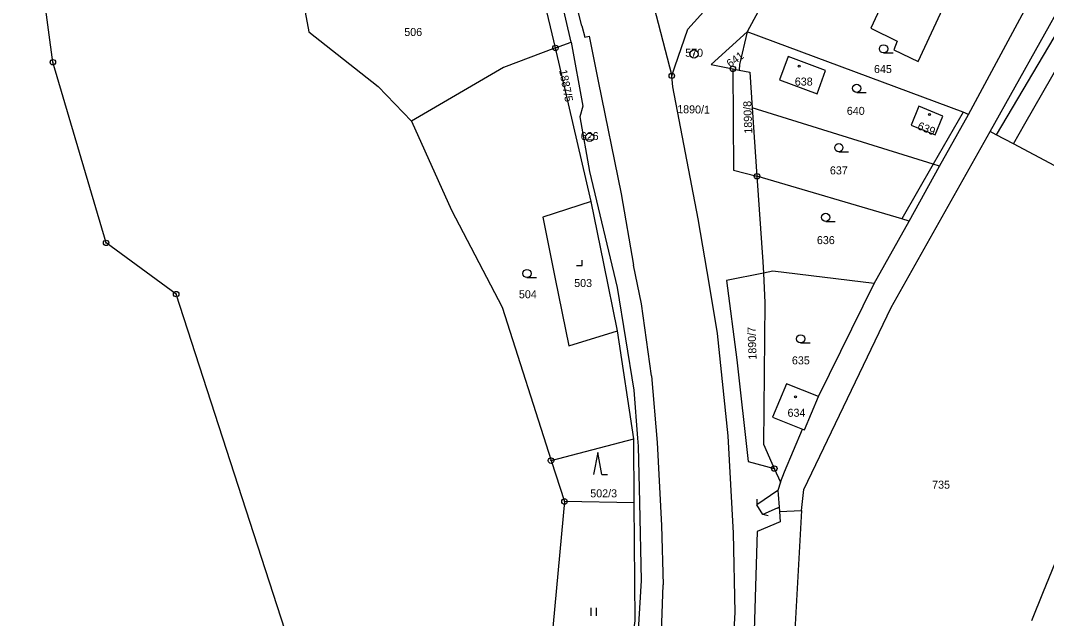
# Model space of a CAD drawing. Extents: x -587171 to -555306, y -1167727 to -1074732.
# Drawn here: x -561154 to -560966.9, y -1078245.7 to -1078136.7 of the extents above; entities that cross this region are included whole.
import ezdxf

# ---------------------------------------------------------------- set-up
doc = ezdxf.new("R2010")
doc.units = 0
for name, color, linetype in [('Hranice parcel', 7, 'Continuous'), ('Parcelní čísla', 7, 'Continuous'), ('Vnitřní kresba', 7, 'Continuous'), ('Značky bodu BP', 7, 'Continuous'), ('Značky budov', 7, 'Continuous'), ('Značky kultur', 7, 'Continuous')]:
    doc.layers.add(name, color=color, linetype=linetype)

msp = doc.modelspace()

# ---------------------------------------------------------------- linework, layer by layer
at = {"layer": 'Hranice parcel'}
for p, q in [((-560977.13, -1078156.96), (-560910.89, -1078038.54)), ((-561148.11, -1078144.33), (-561154.01, -1078101.01)), ((-561043.98, -1078112.78), (-561035.21, -1078146.81)), ((-561056.43, -1078141.73), (-561059.87, -1078127.04)), ((-560981.07, -1078153.84), (-560968.87, -1078131.15)), ((-561056.43, -1078141.73), (-561053.55, -1078140.65)), ((-561049.89, -1078169.71), (-561056.43, -1078141.73)), ((-561138.4, -1078177.27), (-561148.11, -1078144.33)), ((-561024.06, -1078145.55), (-561022.91, -1078145.77)), ((-561020.54, -1078152.65), (-561019.67, -1078165.12)), ((-560986.35, -1078163.3), (-560981.07, -1078153.84)), ((-560976.01, -1078157.56), (-560977.13, -1078156.96)), ((-560991.93, -1078173.29), (-560986.35, -1078163.3)), ((-560998.29, -1078184.68), (-560991.93, -1078173.29)), ((-561125.62, -1078186.6), (-561138.4, -1078177.27)), ((-561008.44, -1078205.27), (-560998.29, -1078184.68)), ((-561104.97, -1078250.29), (-561125.62, -1078186.6)), ((-561042.15, -1078212.99), (-561045.13, -1078193.29)), ((-561057.23, -1078216.95), (-561042.15, -1078212.99)), ((-561042.06, -1078224.67), (-561042.15, -1078212.99)), ((-561057.23, -1078216.95), (-561054.78, -1078224.4)), ((-561016.5, -1078218.4), (-561015.39, -1078220.87)), ((-561054.78, -1078224.4), (-561058.99, -1078270.19)), ((-561042.06, -1078224.67), (-561054.78, -1078224.4)), ((-561015.53, -1078226.21), (-561011.54, -1078226.03))]:
    msp.add_line(p, q, dxfattribs=at)
for points in [[(-560908.67, -1078040.79), (-560924.44, -1078068.27), (-560954.01, -1078120.4), (-560976.01, -1078157.56)], [(-561053.55, -1078140.65), (-561056.92, -1078126.21), (-561057.05, -1078125.67), (-561058.05, -1078121.38), (-561060.21, -1078112.16)], [(-561035.21, -1078146.81), (-561034.65, -1078145.19), (-561032.27, -1078138.29), (-561028.24, -1078133.88), (-561024.17, -1078130.17), (-561021.74, -1078127.95), (-561010.41, -1078116.7), (-561009.61, -1078117.23)], [(-561009.61, -1078117.23), (-561013.13, -1078123.34), (-561021.47, -1078138.82)], [(-561009.61, -1078117.23), (-560997.53, -1078125.17), (-560993.06, -1078128.98), (-560994.02, -1078130.97), (-560995.28, -1078130.38), (-560998.88, -1078138.14), (-560994.07, -1078140.47), (-560994.72, -1078142.08), (-560990.24, -1078144.19), (-560984.97, -1078132.79), (-560984.43, -1078132.92), (-560981.32, -1078128.98), (-560980.88, -1078129.23), (-560976.07, -1078131.9), (-560974.09, -1078128.34)], [(-561104.06, -1078123.41), (-561104.22, -1078123.81), (-561101.44, -1078138.77), (-561088.79, -1078148.79), (-561082.66, -1078155.08)], [(-561021.47, -1078138.82), (-561028.03, -1078144.77), (-561024.4, -1078145.48), (-561024.06, -1078145.55)], [(-561021.47, -1078138.82), (-561022.87, -1078144.77), (-561022.91, -1078145.77)], [(-560981.07, -1078153.84), (-560982.07, -1078153.42), (-561021.47, -1078138.82)], [(-561053.55, -1078140.65), (-561051.45, -1078152.35), (-561051.98, -1078154.3), (-561050.19, -1078164.24), (-561045.16, -1078185.37), (-561042.13, -1078204.1), (-561041.45, -1078212.84), (-561041.34, -1078214.3), (-561041.1, -1078224.57), (-561040.77, -1078238.78), (-561041.98, -1078259), (-561044.39, -1078277.71), (-561044.76, -1078279.73)], [(-561056.43, -1078141.73), (-561065.93, -1078145.3), (-561082.66, -1078155.08)], [(-561015.56, -1078147.57), (-561008.67, -1078150.11), (-561007.18, -1078145.85), (-561013.98, -1078143.3), (-561015.56, -1078147.57)], [(-561026.87, -1078193.78), (-561028.35, -1078184.97), (-561030.37, -1078172.87), (-561034.99, -1078148.81), (-561035.21, -1078146.81)], [(-561024.06, -1078145.55), (-561023.97, -1078164.01), (-561019.67, -1078165.12)], [(-561022.91, -1078145.77), (-561020.99, -1078146.15), (-561020.54, -1078152.65)], [(-560985.77, -1078154.18), (-560990.13, -1078152.36), (-560991.51, -1078155.82), (-560987.15, -1078157.56), (-560985.77, -1078154.18)], [(-560986.35, -1078163.3), (-560987.51, -1078162.94), (-561020.54, -1078152.65)], [(-561082.66, -1078155.08), (-561075.39, -1078171.3), (-561066.15, -1078188.99), (-561057.23, -1078216.95)], [(-561011.54, -1078226.03), (-561011.13, -1078222.23), (-560995.19, -1078189.03), (-560977.13, -1078156.96)], [(-560939.86, -1078176.8), (-560972.88, -1078159.23), (-560976.01, -1078157.56)], [(-560991.93, -1078173.29), (-560993.22, -1078172.91), (-561019.67, -1078165.12)], [(-561019.67, -1078165.12), (-561018.59, -1078180.74), (-561018.5, -1078182.77)], [(-561049.89, -1078169.71), (-561058.74, -1078172.55), (-561056.47, -1078183.81), (-561054.01, -1078196.06), (-561045.13, -1078193.29)], [(-561045.13, -1078193.29), (-561047.6, -1078181.03), (-561049.89, -1078169.71)], [(-561018.5, -1078182.77), (-561025.21, -1078184.1), (-561023.35, -1078198.56), (-561021.28, -1078217.09), (-561016.5, -1078218.4)], [(-560998.29, -1078184.68), (-561016.77, -1078182.43), (-561018.5, -1078182.77)], [(-561018.5, -1078182.77), (-561018.25, -1078188.18), (-561018.5, -1078213.97), (-561016.5, -1078218.4)], [(-561035.16, -1078324.74), (-561033.82, -1078316.71), (-561030.08, -1078297.81), (-561028.46, -1078288.14), (-561026.16, -1078272.82), (-561024.34, -1078256.49), (-561023.62, -1078244.61), (-561023.93, -1078230.17), (-561024.93, -1078212.43), (-561026.87, -1078193.78)], [(-561008.44, -1078205.27), (-561014.25, -1078202.97), (-561016.84, -1078209.03), (-561011.35, -1078211.2)], [(-561011.35, -1078211.2), (-561010.98, -1078211.35), (-561008.44, -1078205.27)], [(-561015.39, -1078220.87), (-561014.66, -1078218.97), (-561011.35, -1078211.2)], [(-561015.39, -1078220.87), (-561015.85, -1078222.41), (-561015.79, -1078223.15)], [(-561015.79, -1078223.15), (-561015.59, -1078225.44), (-561015.53, -1078226.21)], [(-561042.93, -1078253.51), (-561041.89, -1078246.13), (-561042.06, -1078224.67)], [(-561011.54, -1078226.03), (-561014.79, -1078284.02), (-561025.09, -1078288.93)], [(-561015.53, -1078226.21), (-561015.46, -1078228.09), (-561019.63, -1078229.86), (-561020.33, -1078253.98), (-561025.09, -1078288.93)], [(-560965.38, -1078235.83), (-560967.44, -1078240.9), (-560969.58, -1078246.18)]]:
    msp.add_lwpolyline(points, dxfattribs=at)
at = {"layer": 'Vnitřní kresba'}
for p, q in [((-560970.79, -1078155.56), (-560906.23, -1078042.52)), ((-561051.61, -1078137.69), (-561051.08, -1078139.78)), ((-561051.08, -1078139.78), (-561050.29, -1078139.6)), ((-561050.29, -1078139.6), (-561048.62, -1078147.81)), ((-561048.62, -1078147.81), (-561044.46, -1078168.33)), ((-560982.07, -1078153.42), (-560987.51, -1078162.94)), ((-560972.88, -1078159.23), (-560970.79, -1078155.56)), ((-560987.51, -1078162.94), (-560993.22, -1078172.91)), ((-561044.46, -1078168.33), (-561042.17, -1078181.33)), ((-561038.91, -1078201.47), (-561037.89, -1078213.66)), ((-561015.85, -1078222.41), (-561019.68, -1078224.99)), ((-561019.68, -1078223.99), (-561019.68, -1078224.99)), ((-561018.6, -1078226.75), (-561019.68, -1078224.99)), ((-561015.96, -1078225.6), (-561015.59, -1078225.44)), ((-561015.96, -1078225.6), (-561018.6, -1078226.75)), ((-561017.64, -1078227.04), (-561018.6, -1078226.75)), ((-561037.3, -1078253.77), (-561036.77, -1078239.59))]:
    msp.add_line(p, q, dxfattribs=at)
for points in [[(-561051.61, -1078137.69), (-561054.73, -1078125.49), (-561055.94, -1078120.76)], [(-561038.91, -1078201.47), (-561040.71, -1078188.36), (-561042.17, -1078181.33)], [(-561037.89, -1078213.66), (-561037.06, -1078228.81), (-561036.77, -1078239.59)]]:
    msp.add_lwpolyline(points, dxfattribs=at)
at = {"layer": 'Značky bodu BP'}
for centre, radius in [((-561056.43, -1078141.73), 0.5), ((-561056.43, -1078141.73), 0.0303), ((-561031.14, -1078142.84), 0.75), ((-561031.14, -1078142.84), 0.03), ((-561148.11, -1078144.33), 0.5), ((-561148.11, -1078144.33), 0.5), ((-561148.11, -1078144.33), 0.0303), ((-561148.11, -1078144.33), 0.0303), ((-561035.21, -1078146.81), 0.5), ((-561035.21, -1078146.81), 0.0303), ((-561024.06, -1078145.55), 0.5), ((-561024.06, -1078145.55), 0.0303), ((-561050.2, -1078158.02), 0.75), ((-561050.2, -1078158.02), 0.03), ((-561019.67, -1078165.12), 0.5), ((-561019.67, -1078165.12), 0.0303), ((-561138.4, -1078177.27), 0.5), ((-561138.4, -1078177.27), 0.5), ((-561138.4, -1078177.27), 0.0303), ((-561138.4, -1078177.27), 0.0303), ((-561125.62, -1078186.6), 0.5), ((-561125.62, -1078186.6), 0.5), ((-561125.62, -1078186.6), 0.0303), ((-561125.62, -1078186.6), 0.0303), ((-561057.23, -1078216.95), 0.5), ((-561057.23, -1078216.95), 0.0303), ((-561016.5, -1078218.4), 0.5), ((-561016.5, -1078218.4), 0.0303), ((-561054.78, -1078224.4), 0.5), ((-561054.78, -1078224.4), 0.0303)]:
    msp.add_circle(centre, radius, dxfattribs=at)
at = {"layer": 'Značky budov'}
for centre in [(-561011.98, -1078145.07), (-560988.18, -1078153.86), (-561012.63, -1078205.33)]:
    msp.add_circle(centre, 0.175, dxfattribs=at)
at = {"layer": 'Značky kultur'}
for p, q in [((-560996.57, -1078142.65), (-560994.82, -1078142.65)), ((-561001.47, -1078149.84), (-560999.72, -1078149.84)), ((-561004.73, -1078160.65), (-561002.98, -1078160.65)), ((-561007.13, -1078173.36), (-561005.38, -1078173.36)), ((-561051.58, -1078181.39), (-561051.58, -1078180.39)), ((-561052.58, -1078181.39), (-561051.58, -1078181.39)), ((-561061.62, -1078183.6), (-561059.87, -1078183.6)), ((-561011.71, -1078195.5), (-561009.96, -1078195.5)), ((-561048.71, -1078215.47), (-561049.46, -1078219.47)), ((-561047.96, -1078219.47), (-561048.71, -1078215.47)), ((-561047.96, -1078219.47), (-561046.96, -1078219.47)), ((-561049.91, -1078245.27), (-561049.91, -1078243.77)), ((-561048.91, -1078245.27), (-561048.91, -1078243.77))]:
    msp.add_line(p, q, dxfattribs=at)
for centre in [(-560996.57, -1078141.9), (-561001.47, -1078149.09), (-561004.73, -1078159.9), (-561007.13, -1078172.61), (-561061.62, -1078182.85), (-561011.71, -1078194.75)]:
    msp.add_circle(centre, 0.75, dxfattribs=at)

# ---------------------------------------------------------------- texts
at = {"layer": 'Parcelní čísla'}
for s, p in [('506', (-561084, -1078139.55)), ('645', (-560998.32, -1078146.31)), ('638', (-561012.76, -1078148.59)), ('640', (-561003.27, -1078153.93)), ('637', (-561006.36, -1078164.78)), ('636', (-561008.73, -1078177.49)), ('503', (-561053.01, -1078185.31)), ('504', (-561063.09, -1078187.36)), ('635', (-561013.29, -1078199.41)), ('634', (-561014.09, -1078208.96)), ('735', (-560987.71, -1078222.07)), ('502/3', (-561050.07, -1078223.65))]:
    msp.add_text(s, height=1.46, dxfattribs=at).set_placement(p)
for s, rotation, p in [('641', 36, (-561024.55, -1078145.37)), ('1887/5', 281, (-561055.76, -1078145.81)), ('1890/1', 359, (-561034.23, -1078153.61)), ('1890/8', 92, (-561020.51, -1078157.33)), ('639', 338, (-560990.52, -1078156.49)), ('1890/7', 92, (-561019.73, -1078198.52))]:
    msp.add_text(s, height=1.46, rotation=rotation, dxfattribs=at).set_placement(p)
at = {"layer": 'Značky bodu BP'}
for s, p in [('570', (-561032.76, -1078143.34)), ('626', (-561051.81, -1078158.52))]:
    msp.add_text(s, height=1.46, dxfattribs=at).set_placement(p)

doc.saveas('drawing.dxf')
